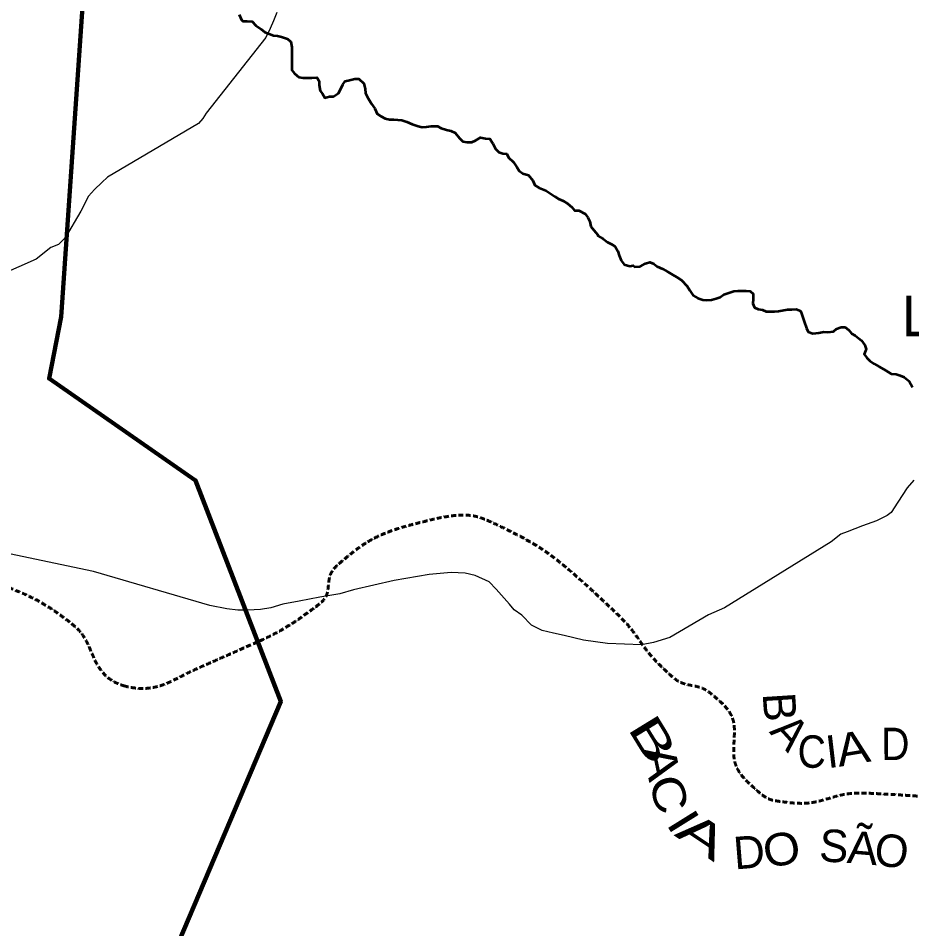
# Model space of a CAD drawing. Extents: x 553962 to 842807, y 8883888 to 9032388.
# Drawn here: x 761992 to 773010, y 8915841 to 8927062 of the extents above; entities that cross this region are included whole.
import ezdxf
from ezdxf.enums import TextEntityAlignment as Align

# ---------------------------------------------------------------- set-up
doc = ezdxf.new("R2010")
doc.units = 0
doc.header["$LTSCALE"] = 20
doc.linetypes.add('MEDIUM_DASHED', pattern=[4.5, 3, -1.5])
for name, color, linetype, lineweight in [('10', 7, 'MEDIUM_DASHED', 60), ('12', 7, 'Continuous', 25), ('24', 7, 'Continuous', 25), ('9', 7, 'Continuous', 90)]:
    doc.layers.add(name, color=color, linetype=linetype, lineweight=lineweight)
doc.layers.add('41', color=7, linetype='Continuous')

msp = doc.modelspace()

# ---------------------------------------------------------------- linework, layer by layer
at = {"layer": '10'}
for points in [[(763310.71, 8918831.32), (762991.96, 8918914.47), (762870.28, 8919444.41), (762584.75, 8919651.94), (762191.5, 8919937.76), (761668.79, 8920107.19), (761308.02, 8920456.27), (760943.97, 8920808.51), (760623.88, 8921203.76), (760267.71, 8921568.14), (760048.52, 8921792.39), (759828.54, 8922010.96), (759582.06, 8922206.88), (759394.56, 8922355.91), (759075.95, 8922159.39), (758872.76, 8922277.85), (758415.9, 8922544.2), (758025.97, 8922940), (757556.74, 8923192.81), (757095.36, 8923441.37), (756624.08, 8923675.7), (756161.79, 8923926.17), (755720.41, 8924165.31), (755288.04, 8924409.56), (754861.41, 8924683.19), (754519.48, 8924902.5), (753816.93, 8925203.56), (753646.75, 8925455.27), (753824.33, 8925847.63), (753765.14, 8926054.92), (753774.92, 8926261.43)], [(780116.15, 8904162.17), (779769.39, 8904177.94), (779422.62, 8904193.71), (779075.85, 8904209.48), (778695.9, 8904226.76), (778318.12, 8904159.82), (777940.98, 8904091.2), (777595.96, 8904028.42), (777262.06, 8903937.23), (776924.32, 8903854.63), (776803.35, 8903825.05), (776686.76, 8903750.37), (776569.67, 8903736.35), (776304.49, 8903704.6), (776099.47, 8903983.3), (775884.02, 8904233.14), (775776.35, 8904358), (775709.21, 8904488.31), (775694.87, 8904611.65), (775670.8, 8904818.6), (776050.43, 8904994.8), (776049.52, 8905226.73), (776047.68, 8905694.49), (775846.84, 8906171.82), (775860.37, 8906646.14), (775878.92, 8907296.23), (776043.6, 8907946.81), (776074.4, 8908597.03), (776108.2, 8909310.28), (775454.34, 8910013.78), (775625.18, 8910702.49), (775746.81, 8911192.83), (776625.71, 8911182.14), (776830.99, 8911648.76), (777030.16, 8912101.51), (777228.07, 8912557.13), (777420.65, 8913014.06), (777556.61, 8913336.63), (777687.59, 8913670.84), (777822.58, 8913983.99), (777919.56, 8914208.95), (778290.17, 8914361.17), (778319.09, 8914551.75), (778353.93, 8914781.35), (778054.25, 8915076.53), (777751.66, 8915261.46), (777515.32, 8915405.89), (777278.58, 8915289.12), (777042.36, 8915285.12), (776916.2, 8915282.98), (776790.12, 8915252.32), (776664.07, 8915261.46), (776484.73, 8915274.46), (776355.68, 8915449.78), (776238.49, 8915592.66), (776104.72, 8915755.73), (776352.41, 8916067), (776214.85, 8916207.73), (776079, 8916346.72), (775768.59, 8916238.74), (775623.77, 8916349.67), (775431.02, 8916497.32), (775387.06, 8916881.69), (775127.26, 8916988.41), (774292.14, 8917331.46), (773439.49, 8917458.06), (772578.86, 8917506.53), (772178.58, 8917529.08), (771773.41, 8917358), (771373.05, 8917411.91), (771257.49, 8917427.47), (771157.31, 8917493.95), (771065.69, 8917577.51), (770748.62, 8917866.67), (770887.06, 8918430.92), (770592.83, 8918689.38), (770430.57, 8918831.91), (770160.08, 8918846.97), (770001.75, 8918996.92), (769746.9, 8919238.26), (769557.21, 8919552.57), (769292.45, 8919801.25), (768866.21, 8920201.59), (768426.67, 8920562.04), (767897.5, 8920818.5), (767600.29, 8920962.53), (767240.04, 8920922.04), (766928.13, 8920842.15), (766587.97, 8920755.03), (766267.79, 8920606.43), (765982.4, 8920369.02), (765805.03, 8920221.47), (765830.93, 8919932.03), (765651.39, 8919801.25), (765249.74, 8919508.69), (764806.41, 8919315.79), (764351.02, 8919115.2), (764017.01, 8918968.08), (763624.43, 8918749.48), (763310.71, 8918831.32)]]:
    msp.add_open_spline(points, degree=3, dxfattribs=at)
at = {"layer": '12'}
for points in [[(765181.33, 8927131.69), (765140.2, 8927029.88), (765099.09, 8926933.17), (765047.75, 8926826.29), (764310.73, 8925890.33), (764269.73, 8925824.18), (764213.47, 8925763.16), (763095.38, 8925102.98), (763023.81, 8925036.89), (762931.8, 8924950.46), (762860.18, 8924869.08), (762762.71, 8924685.88), (762573, 8924355.11), (762491.19, 8924273.75), (762394.27, 8924238.27), (762215.43, 8924090.87), (761786.81, 8923903.18)], [(773035.98, 8921371.1), (772954.12, 8921274.46), (772836.29, 8921096.38), (772754.32, 8920969.18), (772708.34, 8920933.61), (772575.64, 8920867.63), (772402.21, 8920806.82), (772213.44, 8920730.75), (772136.93, 8920705.42), (772014.31, 8920608.86), (770702.08, 8919796.22), (770503.08, 8919709.98), (770028.28, 8919430.68), (769824.28, 8919369.93), (769676.44, 8919339.64), (769258.76, 8919355.69), (768963.44, 8919396.98), (768724.21, 8919453.46), (768591.87, 8919484.27), (768454.44, 8919515.08), (768322.23, 8919581.55), (768200.42, 8919704.03), (768108.96, 8919770.42), (768048.09, 8919841.85), (767885.75, 8920025.54), (767799.49, 8920117.39), (767626.56, 8920194.12), (767504.41, 8920224.91), (767331.22, 8920230.32), (767061.13, 8920205.35), (766627.85, 8920134.83), (766128.18, 8920018.58), (765959.88, 8919967.95), (765710.11, 8919927.66), (765455.21, 8919877.19), (765256.4, 8919841.89), (765108.49, 8919796.32), (764981.06, 8919776.18), (764823.1, 8919766.28), (764700.84, 8919766.51), (764563.35, 8919782.04), (764354.63, 8919823.18), (762919.57, 8920243.53), (760318.37, 8920788.29)]]:
    msp.add_lwpolyline(points, dxfattribs=at)
at = {"layer": '24', "lineweight": 53}
for points in [[(764715.63, 8927107.59), (764745.96, 8927043.84), (764764.12, 8927025.81), (764814.98, 8927025.48), (764875.98, 8927019.99), (764921.44, 8926973.86), (764987.24, 8926927.59), (765032.77, 8926891.64), (765088.57, 8926870.91), (765139.29, 8926850.21), (765190.12, 8926844.79), (765240.91, 8926834.28), (765311.93, 8926808.35), (765352.38, 8926772.43)], [(765352.38, 8926772.43), (765367.18, 8926706.12), (765366.83, 8926655.18), (765366.3, 8926578.78), (765365.67, 8926487.09), (765365.22, 8926420.88), (765400.54, 8926379.9), (765451.08, 8926333.73), (765501.91, 8926328.31), (765557.85, 8926327.95), (765613.8, 8926327.59), (765674.87, 8926332.29), (765705.07, 8926286.26), (765704.72, 8926235.32), (765714.43, 8926169.04), (765744.67, 8926128.09), (765774.87, 8926082.05), (765830.92, 8926096.98), (765881.78, 8926096.65), (765943.09, 8926137.01), (765974.03, 8926197.93), (765994.69, 8926243.65), (766025.48, 8926284.2), (766076.45, 8926299.16), (766142.67, 8926314.01), (766193.53, 8926313.69), (766254.17, 8926257.26), (766268.98, 8926190.95), (766273.71, 8926139.98), (766298.79, 8926088.88), (766349.09, 8926007.06), (766389.39, 8925950.77), (766419.45, 8925884.35), (766465.02, 8925853.5), (766515.7, 8925827.7), (766571.54, 8925812.06), (766622.4, 8925811.74)], [(766622.4, 8925811.74), (766673.26, 8925811.41), (766724.09, 8925805.99), (766784.98, 8925785.22), (766850.89, 8925754.24), (766921.95, 8925733.41), (766972.7, 8925717.8), (767028.68, 8925722.54), (767084.7, 8925732.36), (767160.99, 8925731.87), (767206.59, 8925706.11), (767272.56, 8925685.31), (767328.44, 8925674.77), (767379.12, 8925648.97), (767434.61, 8925582.4), (767475.02, 8925541.39), (767525.85, 8925535.97), (767586.88, 8925535.58), (767632.79, 8925555.66), (767694.07, 8925590.92), (767755.03, 8925580.34), (767805.85, 8925574.92), (767846.16, 8925518.63), (767876.22, 8925452.22), (767916.62, 8925411.21), (767967.38, 8925395.6), (768018.2, 8925390.18), (768038.23, 8925344.21), (768098.88, 8925287.79), (768139.15, 8925226.4), (768169.35, 8925180.36), (768214.91, 8925149.51), (768285.97, 8925128.68), (768336.38, 8925062.13), (768361.42, 8925005.94), (768417.12, 8924969.93), (768498.29, 8924938.84), (768548.94, 8924907.95), (768609.69, 8924866.81), (768655.25, 8924835.96), (768711.02, 8924810.13), (768766.76, 8924779.21), (768817.3, 8924733.04), (768852.62, 8924692.06), (768903.48, 8924691.74), (768984.58, 8924650.47), (769014.78, 8924604.43), (769039.89, 8924558.42), (769054.73, 8924497.2), (769108.58, 8924423.56), (769140.46, 8924391.64), (769140.46, 8924381), (769206.26, 8924343.41), (769256.84, 8924302.34), (769308.18, 8924278.49), (769354.97, 8924247.26), (769386.17, 8924192.6), (769401.77, 8924137.94), (769425.16, 8924075.48), (769464.16, 8924028.63), (769534.35, 8924005.2), (769573.34, 8924013.01), (769596.74, 8923997.4), (769661.68, 8924004.3), (769728.05, 8924039.53)], [(769728.05, 8924039.53), (769779.01, 8924054.48), (769829.73, 8924033.78), (769870.21, 8924002.96), (769936.11, 8923971.98), (770001.99, 8923935.9), (770062.77, 8923899.85), (770113.42, 8923868.96), (770169.12, 8923832.95), (770239.84, 8923761.18), (770275.05, 8923704.92), (770315.32, 8923643.54), (770371.06, 8923612.62), (770431.95, 8923591.85), (770482.77, 8923586.43), (770538.75, 8923591.16), (770599.89, 8923606.05), (770645.8, 8923626.13), (770691.79, 8923656.4), (770752.96, 8923676.39), (770814.13, 8923696.37), (770870.11, 8923701.1), (770966.74, 8923700.48), (771017.6, 8923700.16), (771052.96, 8923664.27), (771052.5, 8923598.06), (771052.15, 8923547.12), (771072.15, 8923496.05), (771117.78, 8923475.39), (771168.61, 8923469.97), (771214.24, 8923449.3), (771265.1, 8923448.97), (771315.96, 8923448.65), (771366.85, 8923453.41), (771478.88, 8923473.07), (771529.74, 8923472.74), (771585.72, 8923477.48)], [(771585.72, 8923477.48), (771636.44, 8923456.78), (771656.47, 8923410.8), (771681.31, 8923324.05), (771711.26, 8923242.36), (771731.29, 8923196.38), (771792.18, 8923175.62), (771863.46, 8923185.35), (771924.56, 8923195.14), (771975.42, 8923194.82), (772046.65, 8923199.45), (772082.5, 8923234.88), (772138.59, 8923254.9), (772189.45, 8923254.57), (772234.98, 8923218.62), (772265.21, 8923177.68), (772310.81, 8923151.91), (772351.29, 8923121.09), (772391.76, 8923090.27), (772432.07, 8923033.98), (772446.97, 8922982.94), (772421.12, 8922921.98), (772456.41, 8922875.91), (772491.77, 8922840.03), (772547.47, 8922804.01), (772613.34, 8922767.93), (772689.31, 8922721.6), (772755.15, 8922680.43), (772816.15, 8922674.94), (772866.9, 8922659.34), (772917.62, 8922638.64), (772978.3, 8922587.31), (773018.5, 8922515.74)]]:
    msp.add_lwpolyline(points, dxfattribs=at)
at = {"layer": '9'}
msp.add_lwpolyline([(763472.95, 8914499.71), (765229.79, 8918639.75), (764179.45, 8921366.33), (762373.1, 8922620.98), (762522.62, 8923380.92), (762953.67, 8929651.11), (762956.16, 8929646.55)], dxfattribs=at)
msp.add_spline([(752845.84, 8918517.4), (763638.29, 8902563.49), (763638.29, 8902563.48)], degree=3, dxfattribs=at)

# ---------------------------------------------------------------- texts
at = {"layer": '10'}
for s, rotation, p in [('B', 273.7, (771182.64, 8918561.94)), ('A', 312.27, (771365.13, 8918132.16)), ('I', 6.726, (772047.45, 8917827.87)), ('S', 356.776, (772039.9, 8916663.05)), ('D', 4.609, (771020.28, 8916587.2)), ('O', 353.119, (772739.54, 8916603.35))]:
    msp.add_text(s, height=400, rotation=rotation, dxfattribs=at).set_placement(p, align=Align.CENTER)
for s, rotation, width, p in [('B', 301.535, 1.6, (769647.14, 8918071.42)), ('D', 0.236, 0.9, (772808.49, 8917919.58)), ('C', 359.4, 0.9, (771774.56, 8917825.1)), ('A', 9.637, 1.15, (772314.84, 8917870.3)), ('A', 282.121, 1.2, (769730.12, 8917844.47)), ('C', 286.413, 1.2, (769824.95, 8917443.27)), ('I', 301.891, 1.25, (770023.84, 8917058.72)), ('A', 326.313, 1.7, (770322.39, 8916826.61)), ('Ã', 355.328, 1.05, (772390.56, 8916638.83)), ('O', 9.637, 1.1, (771437.97, 8916625.61))]:
    msp.add_text(s, height=400, rotation=rotation, dxfattribs=dict(at, width=width)).set_placement(p, align=Align.CENTER)
at = {"layer": '41'}
msp.add_text('Limoeiro de Anadia', height=500, dxfattribs=at).set_placement((772887.99, 8923143.21))

doc.saveas('drawing.dxf')
